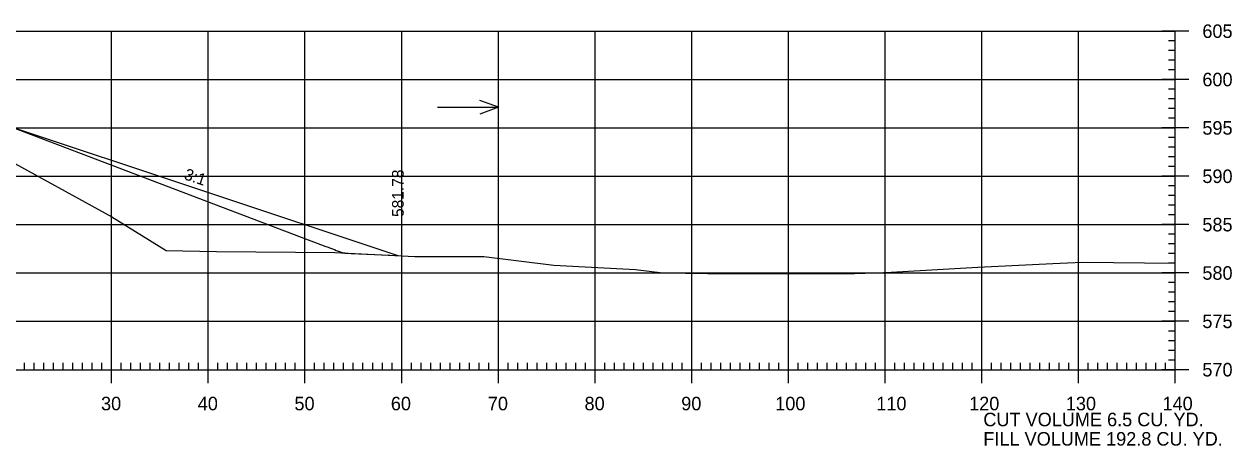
# Model space of a CAD drawing. Extents: x 961436 to 1372525, y 380079 to 2027791.
# Drawn here: x 1371932.3 to 1372057.2, y 380547.9 to 380591.5 of the extents above; entities that cross this region are included whole.
import ezdxf

# ---------------------------------------------------------------- set-up
doc = ezdxf.new("R2010")
doc.units = 0
for name, color, linetype in [('R_Alt Surface', 7, 'Continuous'), ('R_Axis', 7, 'Continuous'), ('R_Axis Annot', 7, 'Continuous'), ('R_Exist Surface', 7, 'Continuous'), ('R_Fin Surface', 7, 'Continuous'), ('R_Fin Surface Annot', 7, 'Continuous'), ('R_Grid', 7, 'Continuous'), ('R_Water Annot', 7, 'Continuous')]:
    doc.layers.add(name, color=color, linetype=linetype)

msp = doc.modelspace()

# ---------------------------------------------------------------- linework, layer by layer
at = {"layer": 'R_Alt Surface'}
msp.add_lwpolyline([(1371930.34, 380581.05), (1371970.95, 380567.52)], dxfattribs=at)
at = {"layer": 'R_Axis'}
for p, q in [((1372052.74, 380590.73), (1372049.94, 380590.73)), ((1372051.34, 380589.73), (1372050.64, 380589.73)), ((1372051.34, 380555.73), (1372051.34, 380590.73)), ((1372051.34, 380588.73), (1372050.64, 380588.73)), ((1372051.34, 380587.73), (1372050.64, 380587.73)), ((1372051.34, 380586.73), (1372050.64, 380586.73)), ((1372052.74, 380585.73), (1372049.94, 380585.73)), ((1372051.34, 380584.73), (1372050.64, 380584.73)), ((1372051.34, 380583.73), (1372050.64, 380583.73)), ((1372051.34, 380582.73), (1372050.64, 380582.73)), ((1372051.34, 380581.73), (1372050.64, 380581.73)), ((1372052.74, 380580.73), (1372049.94, 380580.73)), ((1372051.34, 380579.73), (1372050.64, 380579.73)), ((1372051.34, 380578.73), (1372050.64, 380578.73)), ((1372051.34, 380577.73), (1372050.64, 380577.73)), ((1372051.34, 380576.73), (1372050.64, 380576.73)), ((1372052.74, 380575.73), (1372049.94, 380575.73)), ((1372051.34, 380574.73), (1372050.64, 380574.73)), ((1372051.34, 380573.73), (1372050.64, 380573.73)), ((1372051.34, 380572.73), (1372050.64, 380572.73)), ((1372051.34, 380571.73), (1372050.64, 380571.73)), ((1372052.74, 380570.73), (1372049.94, 380570.73)), ((1372051.34, 380569.73), (1372050.64, 380569.73)), ((1372051.34, 380568.73), (1372050.64, 380568.73)), ((1372051.34, 380567.73), (1372050.64, 380567.73)), ((1372051.34, 380566.73), (1372050.64, 380566.73)), ((1372052.74, 380565.73), (1372049.94, 380565.73)), ((1372051.34, 380564.73), (1372050.64, 380564.73)), ((1372051.34, 380563.73), (1372050.64, 380563.73)), ((1372051.34, 380562.73), (1372050.64, 380562.73)), ((1372051.34, 380561.73), (1372050.64, 380561.73)), ((1372052.74, 380560.73), (1372049.94, 380560.73)), ((1372051.34, 380559.73), (1372050.64, 380559.73)), ((1372051.34, 380558.73), (1372050.64, 380558.73)), ((1372051.34, 380557.73), (1372050.64, 380557.73)), ((1371932.34, 380555.73), (1371932.34, 380556.43)), ((1371933.34, 380555.73), (1371933.34, 380556.43)), ((1371934.34, 380555.73), (1371934.34, 380556.43)), ((1371935.34, 380555.73), (1371935.34, 380556.43)), ((1371936.34, 380555.73), (1371936.34, 380556.43)), ((1371937.34, 380555.73), (1371937.34, 380556.43)), ((1371938.34, 380555.73), (1371938.34, 380556.43)), ((1371939.34, 380555.73), (1371939.34, 380556.43)), ((1371940.34, 380555.73), (1371940.34, 380556.43)), ((1371941.34, 380554.33), (1371941.34, 380557.13)), ((1371942.34, 380555.73), (1371942.34, 380556.43)), ((1371943.34, 380555.73), (1371943.34, 380556.43)), ((1371944.34, 380555.73), (1371944.34, 380556.43)), ((1371945.34, 380555.73), (1371945.34, 380556.43)), ((1371946.34, 380555.73), (1371946.34, 380556.43)), ((1371947.34, 380555.73), (1371947.34, 380556.43)), ((1371948.34, 380555.73), (1371948.34, 380556.43)), ((1371949.34, 380555.73), (1371949.34, 380556.43)), ((1371950.34, 380555.73), (1371950.34, 380556.43)), ((1371951.34, 380554.33), (1371951.34, 380557.13)), ((1371952.34, 380555.73), (1371952.34, 380556.43)), ((1371953.34, 380555.73), (1371953.34, 380556.43)), ((1371954.34, 380555.73), (1371954.34, 380556.43)), ((1371955.34, 380555.73), (1371955.34, 380556.43)), ((1371956.34, 380555.73), (1371956.34, 380556.43)), ((1371957.34, 380555.73), (1371957.34, 380556.43)), ((1371958.34, 380555.73), (1371958.34, 380556.43)), ((1371959.34, 380555.73), (1371959.34, 380556.43)), ((1371960.34, 380555.73), (1371960.34, 380556.43)), ((1371961.34, 380554.33), (1371961.34, 380557.13)), ((1371962.34, 380555.73), (1371962.34, 380556.43)), ((1371963.34, 380555.73), (1371963.34, 380556.43)), ((1371964.34, 380555.73), (1371964.34, 380556.43)), ((1371965.34, 380555.73), (1371965.34, 380556.43)), ((1371966.34, 380555.73), (1371966.34, 380556.43)), ((1371967.34, 380555.73), (1371967.34, 380556.43)), ((1371968.34, 380555.73), (1371968.34, 380556.43)), ((1371969.34, 380555.73), (1371969.34, 380556.43)), ((1371970.34, 380555.73), (1371970.34, 380556.43)), ((1371971.34, 380554.33), (1371971.34, 380557.13)), ((1371972.34, 380555.73), (1371972.34, 380556.43)), ((1371973.34, 380555.73), (1371973.34, 380556.43)), ((1371974.34, 380555.73), (1371974.34, 380556.43)), ((1371975.34, 380555.73), (1371975.34, 380556.43)), ((1371976.34, 380555.73), (1371976.34, 380556.43)), ((1371977.34, 380555.73), (1371977.34, 380556.43)), ((1371978.34, 380555.73), (1371978.34, 380556.43)), ((1371979.34, 380555.73), (1371979.34, 380556.43)), ((1371980.34, 380555.73), (1371980.34, 380556.43)), ((1371981.34, 380554.33), (1371981.34, 380557.13)), ((1371982.34, 380555.73), (1371982.34, 380556.43)), ((1371983.34, 380555.73), (1371983.34, 380556.43)), ((1371984.34, 380555.73), (1371984.34, 380556.43)), ((1371985.34, 380555.73), (1371985.34, 380556.43)), ((1371986.34, 380555.73), (1371986.34, 380556.43)), ((1371987.34, 380555.73), (1371987.34, 380556.43)), ((1371988.34, 380555.73), (1371988.34, 380556.43)), ((1371989.34, 380555.73), (1371989.34, 380556.43)), ((1371990.34, 380555.73), (1371990.34, 380556.43)), ((1371991.34, 380554.33), (1371991.34, 380557.13)), ((1371992.34, 380555.73), (1371992.34, 380556.43)), ((1371993.34, 380555.73), (1371993.34, 380556.43)), ((1371994.34, 380555.73), (1371994.34, 380556.43)), ((1371995.34, 380555.73), (1371995.34, 380556.43)), ((1371996.34, 380555.73), (1371996.34, 380556.43)), ((1371997.34, 380555.73), (1371997.34, 380556.43)), ((1371998.34, 380555.73), (1371998.34, 380556.43)), ((1371999.34, 380555.73), (1371999.34, 380556.43)), ((1372000.34, 380555.73), (1372000.34, 380556.43)), ((1372001.34, 380554.33), (1372001.34, 380557.13)), ((1372002.34, 380555.73), (1372002.34, 380556.43)), ((1372003.34, 380555.73), (1372003.34, 380556.43)), ((1372004.34, 380555.73), (1372004.34, 380556.43)), ((1372005.34, 380555.73), (1372005.34, 380556.43)), ((1372006.34, 380555.73), (1372006.34, 380556.43)), ((1372007.34, 380555.73), (1372007.34, 380556.43)), ((1372008.34, 380555.73), (1372008.34, 380556.43)), ((1372009.34, 380555.73), (1372009.34, 380556.43)), ((1372010.34, 380555.73), (1372010.34, 380556.43)), ((1372011.34, 380554.33), (1372011.34, 380557.13)), ((1372012.34, 380555.73), (1372012.34, 380556.43)), ((1372013.34, 380555.73), (1372013.34, 380556.43)), ((1372014.34, 380555.73), (1372014.34, 380556.43)), ((1372015.34, 380555.73), (1372015.34, 380556.43)), ((1372016.34, 380555.73), (1372016.34, 380556.43)), ((1372017.34, 380555.73), (1372017.34, 380556.43)), ((1372018.34, 380555.73), (1372018.34, 380556.43)), ((1372019.34, 380555.73), (1372019.34, 380556.43)), ((1372020.34, 380555.73), (1372020.34, 380556.43)), ((1372021.34, 380554.33), (1372021.34, 380557.13)), ((1372022.34, 380555.73), (1372022.34, 380556.43)), ((1372023.34, 380555.73), (1372023.34, 380556.43)), ((1372024.34, 380555.73), (1372024.34, 380556.43)), ((1372025.34, 380555.73), (1372025.34, 380556.43)), ((1372026.34, 380555.73), (1372026.34, 380556.43)), ((1372027.34, 380555.73), (1372027.34, 380556.43)), ((1372028.34, 380555.73), (1372028.34, 380556.43)), ((1372029.34, 380555.73), (1372029.34, 380556.43)), ((1372030.34, 380555.73), (1372030.34, 380556.43)), ((1372031.34, 380554.33), (1372031.34, 380557.13)), ((1372032.34, 380555.73), (1372032.34, 380556.43)), ((1372033.34, 380555.73), (1372033.34, 380556.43)), ((1372034.34, 380555.73), (1372034.34, 380556.43)), ((1372035.34, 380555.73), (1372035.34, 380556.43)), ((1372036.34, 380555.73), (1372036.34, 380556.43)), ((1372037.34, 380555.73), (1372037.34, 380556.43)), ((1372038.34, 380555.73), (1372038.34, 380556.43)), ((1372039.34, 380555.73), (1372039.34, 380556.43)), ((1372040.34, 380555.73), (1372040.34, 380556.43)), ((1372041.34, 380554.33), (1372041.34, 380557.13)), ((1372042.34, 380555.73), (1372042.34, 380556.43)), ((1372043.34, 380555.73), (1372043.34, 380556.43)), ((1372044.34, 380555.73), (1372044.34, 380556.43)), ((1372045.34, 380555.73), (1372045.34, 380556.43)), ((1372046.34, 380555.73), (1372046.34, 380556.43)), ((1372047.34, 380555.73), (1372047.34, 380556.43)), ((1372048.34, 380555.73), (1372048.34, 380556.43)), ((1372049.34, 380555.73), (1372049.34, 380556.43)), ((1372050.34, 380555.73), (1372050.34, 380556.43)), ((1372051.34, 380556.73), (1372050.64, 380556.73)), ((1372051.34, 380554.33), (1372051.34, 380557.13)), ((1371771.34, 380555.73), (1372051.34, 380555.73)), ((1372052.74, 380555.73), (1372049.94, 380555.73))]:
    msp.add_line(p, q, dxfattribs=at)
at = {"layer": 'R_Exist Surface'}
msp.add_lwpolyline([(1371929.95, 380577.82), (1371941.36, 380571.53), (1371946.99, 380568.07), (1371952.19, 380567.95), (1371964.42, 380567.85), (1371972.71, 380567.43), (1371979.82, 380567.42), (1371987.09, 380566.52), (1371995.52, 380566.08), (1371998.33, 380565.76), (1372003, 380565.69), (1372007.24, 380565.66), (1372018.17, 380565.66), (1372020.39, 380565.76), (1372021.95, 380565.81), (1372030.92, 380566.32), (1372038.67, 380566.7), (1372040.19, 380566.78), (1372041.77, 380566.86), (1372051.34, 380566.76)], dxfattribs=at)
at = {"layer": 'R_Fin Surface'}
msp.add_lwpolyline([(1371930.84, 380580.89), (1371961.66, 380569.17), (1371963.49, 380568.48), (1371963.63, 380568.42), (1371964.08, 380568.25), (1371964.38, 380568.14), (1371964.55, 380568.07), (1371964.67, 380568.03), (1371964.76, 380568), (1371964.82, 380567.97), (1371965.2, 380567.85), (1371965.37, 380567.8), (1371965.38, 380567.8), (1371965.4, 380567.8), (1371965.43, 380567.8), (1371965.47, 380567.79), (1371965.53, 380567.79), (1371965.63, 380567.78), (1371965.67, 380567.78), (1371966.07, 380567.76), (1371970.95, 380567.52)], dxfattribs=at)
at = {"layer": 'R_Grid'}
for p, q in [((1371771.34, 380590.73), (1372051.34, 380590.73)), ((1371941.34, 380555.73), (1371941.34, 380590.73)), ((1371951.34, 380555.73), (1371951.34, 380590.73)), ((1371961.34, 380555.73), (1371961.34, 380590.73)), ((1371971.34, 380555.73), (1371971.34, 380590.73)), ((1371981.34, 380555.73), (1371981.34, 380590.73)), ((1371991.34, 380555.73), (1371991.34, 380590.73)), ((1372001.34, 380555.73), (1372001.34, 380590.73)), ((1372011.34, 380555.73), (1372011.34, 380590.73)), ((1372021.34, 380555.73), (1372021.34, 380590.73)), ((1372031.34, 380555.73), (1372031.34, 380590.73)), ((1372041.34, 380555.73), (1372041.34, 380590.73)), ((1372051.34, 380555.73), (1372051.34, 380590.73)), ((1371771.34, 380585.73), (1372051.34, 380585.73)), ((1371771.34, 380580.73), (1372051.34, 380580.73)), ((1371771.34, 380575.73), (1372051.34, 380575.73)), ((1371771.34, 380570.73), (1372051.34, 380570.73)), ((1371771.34, 380565.73), (1372051.34, 380565.73)), ((1371771.34, 380560.73), (1372051.34, 380560.73)), ((1371771.34, 380555.73), (1372051.34, 380555.73))]:
    msp.add_line(p, q, dxfattribs=at)
at = {"layer": 'R_Water Annot'}
for p, q in [((1371981.34, 380582.86), (1371979.41, 380583.56)), ((1371975.05, 380582.86), (1371981.34, 380582.86)), ((1371981.34, 380582.86), (1371979.41, 380582.16))]:
    msp.add_line(p, q, dxfattribs=at)

# ---------------------------------------------------------------- texts
at = {"layer": 'R_Axis Annot'}
for s, p in [('605', (1372054.14, 380590.03)), ('600', (1372054.14, 380585.03)), ('595', (1372054.14, 380580.03)), ('590', (1372054.14, 380575.03)), ('585', (1372054.14, 380570.03)), ('580', (1372054.14, 380565.03)), ('575', (1372054.14, 380560.03)), ('570', (1372054.14, 380555.03)), ('30', (1371940.25, 380551.53)), ('40', (1371950.25, 380551.53)), ('50', (1371960.25, 380551.53)), ('60', (1371970.22, 380551.53)), ('70', (1371980.25, 380551.53)), ('80', (1371990.25, 380551.53)), ('90', (1372000.25, 380551.53)), ('100', (1372009.97, 380551.53)), ('110', (1372020.42, 380551.53)), ('120', (1372030.02, 380551.53)), ('130', (1372040.02, 380551.53)), ('140', (1372050.02, 380551.53)), ('CUT VOLUME 6.5 CU. YD.', (1372031.49, 380549.88)), ('FILL VOLUME 192.8 CU. YD.', (1372031.49, 380547.88))]:
    msp.add_text(s, height=1.4, dxfattribs=at).set_placement(p)
at = {"layer": 'R_Fin Surface Annot'}
for s, rotation, p in [('3:1', 341.5651, (1371948.76, 380575.44)), ('581.78', 90, (1371971.55, 380571.52)), ('581.78', 90, (1371971.55, 380571.52))]:
    msp.add_text(s, height=1.2, rotation=rotation, dxfattribs=at).set_placement(p)

doc.saveas('drawing.dxf')
